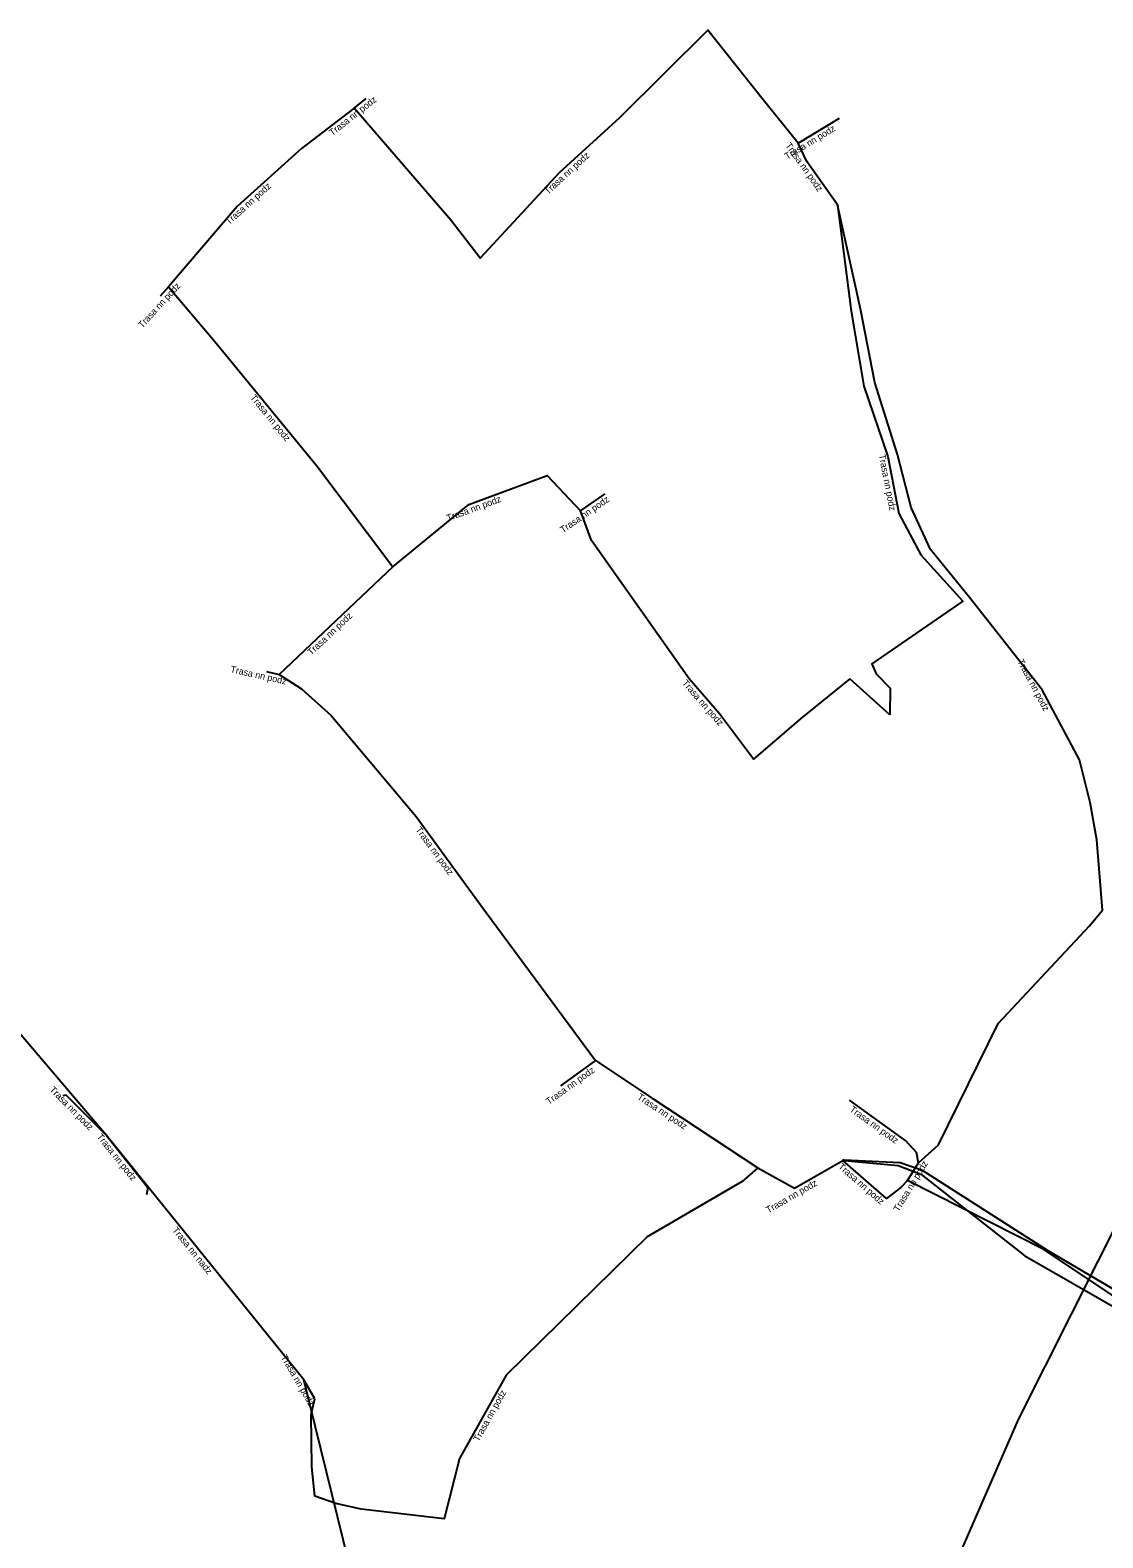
# Model space of a CAD drawing. Extents: x -682739 to -681564, y -1060091 to -1059590.
# Drawn here: x -682665.4 to -682585.3, y -1059757.4 to -1059644.9 of the extents above; entities that cross this region are included whole.
import ezdxf

# ---------------------------------------------------------------- set-up
doc = ezdxf.new("R2010")
doc.units = 0
for name, color, linetype in [('Popiskový text - Ostatní atributy Trasy', 7, 'Continuous'), ('Spojnice NN', 7, 'Continuous'), ('Spojnice VN', 7, 'Continuous')]:
    doc.layers.add(name, color=color, linetype=linetype)

msp = doc.modelspace()

# ---------------------------------------------------------------- linework, layer by layer
at = {"layer": 'Spojnice NN'}
for points in [[(-682608.06, -1059653.34), (-682610.77, -1059649.99), (-682614.81, -1059644.91), (-682621.41, -1059651.46), (-682625.9, -1059655.56), (-682631.81, -1059661.94), (-682633.99, -1059659.09), (-682641.22, -1059650.73)], [(-682641.22, -1059650.73), (-682645.15, -1059653.74), (-682649.94, -1059658.06), (-682655.07, -1059664.08)], [(-682641.22, -1059650.73), (-682640.32, -1059650.02)], [(-682608.06, -1059653.34), (-682604.98, -1059651.48)], [(-682605.11, -1059657.96), (-682607.4, -1059654.72), (-682608.06, -1059653.34)], [(-682599.07, -1059729.44), (-682597.57, -1059728.1), (-682593.11, -1059719.04), (-682586.3, -1059711.75), (-682585.33, -1059710.58), (-682585.75, -1059705.34), (-682586.25, -1059702.55), (-682587.05, -1059699.38), (-682589.83, -1059694.15), (-682595.27, -1059687.25), (-682598.17, -1059683.68), (-682599.61, -1059680.54), (-682600.64, -1059676.57), (-682602.33, -1059671.21), (-682603.41, -1059665.72), (-682605.11, -1059657.96)], [(-682605.11, -1059657.96), (-682604.1, -1059665.89), (-682603.15, -1059671.47), (-682601.36, -1059676.72), (-682600.53, -1059680.98), (-682598.9, -1059684.08), (-682595.76, -1059687.52), (-682602.55, -1059692.2), (-682602.23, -1059692.94), (-682601.19, -1059694.01), (-682601.21, -1059696.01)], [(-682655.07, -1059664.08), (-682655.7, -1059664.77)], [(-682655.07, -1059664.08), (-682651.61, -1059668.15), (-682644, -1059677.44), (-682638.32, -1059684.97)], [(-682638.32, -1059684.97), (-682632.66, -1059680.32), (-682626.8, -1059678.15), (-682624.32, -1059680.78)], [(-682624.32, -1059680.78), (-682622.48, -1059679.51)], [(-682601.21, -1059696.01), (-682604.2, -1059693.32), (-682607.86, -1059696.29), (-682611.38, -1059699.32), (-682613.92, -1059695.94), (-682616.19, -1059693.33), (-682623.48, -1059682.99), (-682624.32, -1059680.78)], [(-682638.32, -1059684.97), (-682646.81, -1059692.99)], [(-682647.75, -1059692.78), (-682646.81, -1059692.99)], [(-682646.81, -1059692.99), (-682645.15, -1059694.07), (-682642.94, -1059696.07), (-682636.59, -1059703.59), (-682631.77, -1059710.19), (-682623.18, -1059721.82)], [(-682659.72, -1059727.41), (-682675.2, -1059709.26)], [(-682623.18, -1059721.82), (-682625.81, -1059723.71)], [(-682623.18, -1059721.82), (-682618.97, -1059724.63), (-682611.06, -1059729.83)], [(-682659.72, -1059727.41), (-682662.73, -1059724.39), (-682662.97, -1059724.45)], [(-682599.07, -1059729.44), (-682599.22, -1059728.69), (-682600.02, -1059727.8), (-682604.23, -1059724.78)], [(-682659.72, -1059727.41), (-682656.62, -1059731.28), (-682656.73, -1059731.83)], [(-682644.98, -1059745.65), (-682659.72, -1059727.41)], [(-682611.06, -1059729.83), (-682612.23, -1059730.85), (-682619.34, -1059734.97), (-682629.87, -1059745.31), (-682633.34, -1059751.52), (-682634.49, -1059756.03), (-682640.7, -1059755.3), (-682642.57, -1059754.87), (-682644.15, -1059754.34), (-682644.37, -1059752.13), (-682644.43, -1059748.23), (-682644.16, -1059747.06)], [(-682611.06, -1059729.83), (-682608.33, -1059731.35), (-682604.72, -1059729.27)], [(-682599.88, -1059730.78), (-682600.4, -1059731.29), (-682601.47, -1059732.11), (-682604.72, -1059729.27)], [(-682599.88, -1059730.78), (-682599.07, -1059729.44)], [(-682447.96, -1059790.21), (-682459.73, -1059794.22), (-682460.78, -1059794.04), (-682462.86, -1059792.75), (-682471.05, -1059793.41), (-682474.96, -1059793.4), (-682481.35, -1059793.46), (-682493.93, -1059791.42), (-682506.56, -1059788.09), (-682521.99, -1059781.45), (-682525.52, -1059778.64), (-682528.18, -1059775.05), (-682529.63, -1059771.35), (-682532.33, -1059768.34), (-682552.54, -1059758.22), (-682567.03, -1059749.33), (-682579.9, -1059742.47), (-682589.71, -1059735.91), (-682599.88, -1059730.78)], [(-682644.16, -1059747.06), (-682644.98, -1059745.65)], [(-682636.98, -1059778.06), (-682644.98, -1059745.65)]]:
    msp.add_lwpolyline(points, dxfattribs=at)
at = {"layer": 'Spojnice VN'}
for points in [[(-682591.59, -1059748.6), (-682547.93, -1059661.89)], [(-682583.22, -1059739.66), (-682589.38, -1059736.03), (-682598.77, -1059730.02), (-682600.45, -1059729.46), (-682604.62, -1059729.26), (-682604.72, -1059729.26), (-682604.72, -1059729.27)], [(-682604.72, -1059729.27), (-682604.72, -1059729.27), (-682604.62, -1059729.27), (-682600.59, -1059729.66), (-682598.9, -1059730.29), (-682591.14, -1059736.39), (-682583.84, -1059740.58)], [(-682617.72, -1059808.48), (-682591.59, -1059748.6)]]:
    msp.add_lwpolyline(points, dxfattribs=at)

# ---------------------------------------------------------------- texts
at = {"layer": 'Popiskový text - Ostatní atributy Trasy'}
for s, rotation, p in [('Trasa nn podz', 38.2695, (-682642.84, -1059652.83)), ('Trasa nn podz', 31.1276, (-682608.88, -1059654.59)), ('Trasa nn podz', 305.2523, (-682609.04, -1059653.52)), ('Trasa nn podz', 42.4005, (-682626.74, -1059657.21)), ('Trasa nn podz', 42.0466, (-682650.55, -1059659.48)), ('Trasa nn podz', 47.6026, (-682657.03, -1059667.19)), ('Trasa nn podz', 309.323, (-682649.01, -1059672.35)), ('Trasa nn podz', 281.0251, (-682602.04, -1059676.62)), ('Trasa nn podz', 20.32, (-682634.2, -1059681.58)), ('Trasa nn podz', 34.6141, (-682625.62, -1059682.47)), ('Trasa nn podz', 43.3694, (-682644.41, -1059691.61)), ('Trasa nn podz', 347.4067, (-682650.49, -1059692.83)), ('Trasa nn podz', 297.9928, (-682591.7, -1059692.02)), ('Trasa nn podz', 311.0145, (-682616.76, -1059693.66)), ('Trasa nn podz', 306.1408, (-682636.66, -1059704.59)), ('Trasa nn podz', 35.7022, (-682626.67, -1059725.13)), ('Trasa nn podz', 314.905, (-682664, -1059724.04)), ('Trasa nn podz', 326.6793, (-682620.12, -1059724.65)), ('Trasa nn podz', 324.3466, (-682604.26, -1059725.56)), ('Trasa nn podz', 308.6959, (-682660.47, -1059727.51)), ('Trasa nn podz', 318.9258, (-682605.11, -1059729.8)), ('Trasa nn podz', 58.848, (-682600.55, -1059733.14)), ('Trasa nn podz', 29.9387, (-682610.28, -1059733.23)), ('Trasa nn nadz', 308.9422, (-682654.83, -1059734.49)), ('Trasa nn podz', 300.1806, (-682646.71, -1059743.96)), ('Trasa nn podz', 60.8046, (-682631.91, -1059750.3))]:
    msp.add_text(s, height=0.5, rotation=rotation, dxfattribs=at).set_placement(p)

doc.saveas('drawing.dxf')
